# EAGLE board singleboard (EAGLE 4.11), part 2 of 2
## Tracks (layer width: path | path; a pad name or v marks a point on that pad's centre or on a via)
-15V  (via drill 0.61)
  Top 0.635: v123.83,21.59 v123.83,16.51
  Bottom 0.635: 180.97,20.32 187.32,13.97 U$1.BB2 | 180.97,20.32 179.71,21.59 v123.83,21.59 55.88,21.59 55.88,13.97 U$1.DB2 | v123.83,16.51 123.83,13.97 U$1.CB2 | 180.97,20.32 250.82,20.32 257.18,13.97 U$1.AB2
A15U1  (via drill 0.61)
  Top 0.254: E2.4 244.47,83.19 244.47,84.46 E2.2 245.75,87 245.75,88.27 E2.1 | E13.10 205.1,78.11 205.1,76.84 E13.9 203.84,74.3 203.84,24.77 v209.55,19.05 | R12.1 R11.2 | E13.5 197.49,79.38 197.49,80.65 E13.4 196.22,83.19 196.22,84.46 E13.2
  Bottom 0.254: E13.12 204.47,83.82 201.93,81.28 E13.4 R12.1 | E13.5 E13.10 207.01,78.74 208.28,77.47 241.3,77.47 245.11,81.28 E2.4 | v209.55,19.05 209.55,13.97 U$1.AU2
A15V1
  Top 0.254: E8.2 212.72,51.44 212.72,52.71 E8.1 | E8.12 R13.2 R14.1 | E2.9 253.37,76.84 253.37,78.11 E2.10 | E8.9 220.34,41.28 220.34,42.55 E8.10
  Bottom 0.254: E8.2 214.63,50.8 217.17,48.26 E8.12 | E2.12 252.09,81.92 252.09,79.38 253.37,79.38 E2.10 | E8.4 214.63,45.72 217.17,43.18 E8.10 222.88,43.18 225.43,45.72 R14.1 | E2.9 260.35,69.85 260.35,39.37 223.52,39.37 222.25,40.64 E8.9
B17S1  (via drill 0.61)
  Top 0.254: E49.1 28.57,87 28.57,83.19 E49.4 33.02,81.28 E49.9 | E12.3 210.82,177.8 210.82,119.38 E10.4 | v177.8,82.55 177.8,114.3 E19.4
  Bottom 0.254: 208.28,115.57 208.91,116.21 212.72,116.21 E10.4 217.17,116.84 219.71,114.3 E10.10 | 208.28,115.57 207.01,114.3 E14.10 | 208.28,115.57 182.88,115.57 181.61,116.84 E19.4 | v177.8,82.55 111.12,82.55 108.58,80.01 80.01,80.01 77.47,77.47 40.64,77.47 39.37,76.2 E49.9
B17V1  (via drill 0.61)
  Top 0.254: E7.3 230.5,118.75 230.5,117.48 E7.4 229.24,114.94 229.24,90.81 E6.1 | E10.1 219.07,124.46 219.07,123.83 E10.13 | R15.2 R16.1 | v19.68,84.46 19.68,57.79 E52.1 | v147.96,90.17 147.96,53.98 E26.1
  Bottom 0.254: E14.13 207.01,121.92 207.65,121.29 211.46,121.29 212.09,120.65 218.44,120.65 219.71,121.92 E10.13 227.33,121.92 229.87,119.38 E7.3 | E6.13 237.49,86.36 234.95,88.9 E6.1 226.69,84.46 226.06,84.46 R15.2 224.79,83.82 222.25,86.36 E9.13 217.17,86.36 214.63,88.9 E9.1 212.09,88.9 210.82,90.17 v147.96,90.17 | E26.13 153.67,50.8 151.13,53.34 E26.1 146.05,53.34 143.51,50.8 E27.13 135.89,50.8 133.35,53.34 E27.1 130.81,53.34 129.54,54.61 21.59,54.61 18.41,51.44 | 18.41,51.44 19.05,50.8 E52.13 | 18.41,51.44 16.51,53.34 E52.1 | 21.59,86.36 19.05,88.9 E53.1 | v19.68,84.46 21.59,86.36 | 21.59,86.36 E53.13
C16U1
  Top 0.254: R24.1 R23.2 | E22.5 164.47,79.38 164.47,80.65 E22.4 163.19,83.19 163.19,84.46 E22.2 | E18.5 179.71,79.38 179.71,80.65 E18.4 | E18.12 187.32,84.46 187.32,85.73 E18.13
  Bottom 0.254: E22.4 R24.1 | E18.5 E18.10 | E18.13 E18.2 179.07,86.36 177.8,87.63 167.64,87.63 166.37,86.36 E22.2 | E18.4 181.61,81.28 184.15,83.82 E18.12
D01BINIT  (via drill 0.61)
  Top 0.254: v184.15,91.44 181.61,88.9 E18.1 | v196.85,91.44 197.49,90.81 197.49,89.54 E13.1 | v167.64,92.71 167.64,114.3 E23.4
  Bottom 0.254: v196.85,91.44 v184.15,91.44 168.91,91.44 v167.64,92.71
D01BTP2L  (via drill 0.61)
  Top 0.254: v178.44,123.19 178.44,145.42 E20.4
  Bottom 0.254: E23.2 166.37,121.92 167.64,123.19 v178.44,123.19 228.6,123.19 229.87,121.92 E7.2 E7.13
D01DEL1H  (via drill 0.61)
  Top 0.254: v170.18,77.47 169.54,78.11 169.54,102.87 | 169.54,102.87 169.54,145.42 E24.3 | v230.5,103.51 233.04,106.05 233.04,112.4 E7.5 | 169.54,102.87 v170.18,102.87
  Bottom 0.254: v170.18,77.47 163.83,77.47 158.12,71.76 106.05,71.76 100.33,77.47 80.01,77.47 77.47,74.93 73.66,74.93 72.39,73.66 E44.8 | v230.5,103.51 229.87,102.87 v170.18,102.87
D01DEL1L  (via drill 0.61)
  Top 0.254: E14.4 196.22,118.75 196.22,145.42 E15.4 | v210.19,110.49 208.91,111.76 v208.91,118.11
  Bottom 0.254: v210.19,110.49 228.6,110.49 229.87,111.76 E7.6 | v208.91,118.11 200.66,118.11 199.39,116.84 E14.4
D01DEL2  (via drill 0.61)
  Top 0.254: 98.42,69.85 v97.16,71.12 | 98.42,69.85 v98.42,57.15 98.42,53.98 E35.1 | v151.13,123.19 151.13,140.97 E24.1 | v102.23,120.65 101.6,120.02 101.6,73.03 98.42,69.85 | v112.39,50.8 109.86,53.34 v109.86,57.15
  Bottom 0.254: v97.16,71.12 69.85,71.12 64.77,76.2 E44.6 | v151.13,123.19 148.59,120.65 v102.23,120.65 | v112.39,50.8 113.03,50.8 115.57,48.26 IC2.1 | v98.42,57.15 v109.86,57.15
D01DEL3  (via drill 0.61)
  Top 0.254: v194.31,80.01 195.58,81.28 195.58,147.32 E15.3
  Bottom 0.254: v194.31,80.01 113.03,80.01 E36.8 | E15.11 204.47,147.32 201.93,149.86 E15.3
D01DEL4  (via drill 0.61)
  Top 0.254: E36.6 100.97,78.11 100.97,122.56 E37.1 | 194.94,147.32 194.94,177.17 E16.3 | 194.94,147.32 194.94,120.02 v194.31,119.38 v194.31,113.03 194.31,93.35 191.77,90.81 191.77,74.93 v186.69,69.85 | 194.94,147.32 v194.31,147.32
  Bottom 0.254: v194.31,119.38 E14.3 | v194.31,113.03 236.22,113.03 237.49,111.76 E7.9 | v194.31,147.32 E20.11 | v186.69,69.85 159.38,69.85 158.12,71.12 105.41,71.12 100.33,76.2 E36.6
D01DEL5  (via drill 0.61)
  Top 0.254: v174.62,125.73 175.9,127 175.9,138.43 177.8,140.34 177.8,147.32 178.44,147.96 | 178.44,147.96 E20.3 | v193.04,171.45 178.44,156.85 178.44,147.96
  Bottom 0.254: v174.62,125.73 168.91,125.73 166.37,123.19 163.83,123.19 158.75,118.11 87.63,118.11 E40.6 | v193.04,171.45 203.2,171.45 204.47,172.72 E16.9
D01DONEH  (via drill 0.61)
  Top 0.254: v176.53,33.02 176.53,105.41 E23.8 | v23.5,22.86 14.61,13.97 U$1.DS1
  Bottom 0.254: v176.53,33.02 166.37,22.86 v23.5,22.86
D01DONEL  (via drill 0.61)
  Top 0.254: v170.81,160.02 170.81,113.67 E23.9 | v135.89,179.71 135.89,182.88 137.16,184.15 E30.7
  Bottom 0.254: E16.8 206.38,170.82 207.65,170.82 207.65,173.36 207.01,173.99 184.78,173.99 v170.81,160.02 150.5,180.34 136.53,180.34 v135.89,179.71
D01INHIBIT  (via drill 0.61)
  Top 0.254: v221.62,15.24 221.62,37.47 E8.8
  Bottom 0.254: v221.62,15.24 222.88,13.97 U$1.AP2
D01INITL  (via drill 0.61)
  Top 0.254: E13.6 200.03,78.11 200.03,122.56 E14.1 200.03,126.37 200.03,146.69 E15.13 | E20.13 189.87,150.5 189.87,123.83 E19.13 186.69,121.92 186.69,122.56 v184.78,124.46
  Bottom 0.254: E15.13 204.47,152.4 201.93,154.94 E15.1 196.85,154.94 195.58,153.67 182.88,153.67 | v184.78,124.46 E19.1 | 182.88,153.67 184.15,152.4 E20.13 | 182.88,153.67 181.61,154.94 E20.1
D01LOADMDL  (via drill 0.61)
  Top 0.254: E49.10 E49.2 | v184.78,172.72 158.75,172.72 140.97,190.5 64.77,190.5 64.77,189.23 54.61,179.07 54.61,91.44 v46.99,83.82
  Bottom 0.254: E49.5 E49.10 41.91,78.74 v46.99,83.82 | v184.78,172.72 E16.6
D01MEMDONEL
  Bottom 0.254: E30.5 138.43,181.61 126.36,181.61 125.09,180.34 H05/H24.28
D01MEMSTARTL  (via drill 0.61)
  Top 0.254: v227.97,106.68 227.97,121.29 E7.1
  Bottom 0.254: E19.10 186.69,114.3 182.88,110.49 167.64,110.49 166.37,111.76 E23.6 163.19,111.76 163.19,108.59 165.1,106.68 v227.97,106.68
D01POWEROK  (via drill 0.61)
  Top 0.254: v134.62,115.57 130.81,111.76 130.81,66.68 128.27,64.14 128.27,27.94 137.16,19.05 v137.16,15.24
  Bottom 0.254: v134.62,115.57 160.02,115.57 163.83,119.38 E23.3 | v137.16,15.24 137.16,13.97 U$1.BV2
D01READH
  Top 0.254: E7.10 238.12,114.94 238.12,116.21 E7.11 236.85,118.75 236.85,125.73 238.12,127 238.12,187.33 237.49,187.96 200.03,187.96 200.03,181.61 | 194.31,173.99 194.31,179.07 196.85,181.61 200.03,181.61 | 194.31,173.99 194.31,171.45 193.04,170.18 193.04,116.84 E19.9 | 200.03,181.61 200.03,179.71 E16.4 197.49,177.17 197.49,175.9 E16.5 | 194.31,173.99 E24.13
  Bottom 0.254: E24.13 E24.2
D01READL  (via drill 0.61)
  Top 0.254: v210.19,178.44 v210.19,111.76 211.46,110.49 211.46,107.95 214,107.95 227.97,93.98 227.97,34.93 v227.33,34.29 | E16.10 205.1,175.9 205.1,177.17 E16.11 | v238.76,15.88 238.12,16.51 v238.12,23.5
  Bottom 0.254: v210.19,111.76 208.91,110.49 190.5,110.49 189.23,109.22 E19.8 | v210.19,178.44 209.55,177.8 E16.11 | v238.76,15.88 236.85,13.97 U$1.AK2 | v238.12,23.5 v227.33,34.29
D01RETURN  (via drill 0.61)
  Top 0.254: v217.81,15.24 217.81,61.6 E13.8
  Bottom 0.254: v217.81,15.24 219.07,13.97 U$1.AR2
D01SELECTH
  Top 0.254: E18.9 186.06,78.11 186.06,100.97 178.44,108.59 178.44,112.4 E19.5
D01SELECTL  (via drill 0.61)
  Top 0.254: v148.59,113.03 146.05,115.57 146.05,168.91 E30.2 137.16,181.61 139.7,184.15 E30.6
  Bottom 0.254: v148.59,113.03 177.8,113.03 179.07,111.76 E19.6
D01SELH  (via drill 0.61)
  Top 0.254: v177.16,128.91 177.16,121.92 E19.2 | v212.09,132.08 211.46,132.72 211.46,140.34 E11.6
  Bottom 0.254: v177.16,128.91 180.34,132.08 v212.09,132.08
D01SELL
  Top 0.254: E11.5 218.44,144.78 218.44,175.26 E12.11
D01SOURCE  (via drill 0.61)
  Top 0.254: v243.84,19.05 243.84,73.66 E2.6
  Bottom 0.254: v243.84,19.05 241.94,17.15 234.31,17.15 232.41,15.24 232.41,13.97 U$1.AL2
D01STROBE  (via drill 0.61)
  Top 0.254: v231.78,66.68 228.6,63.5 228.6,17.78 229.87,16.51 v229.87,15.24
  Bottom 0.254: v231.78,66.68 245.75,66.68 252.73,73.66 E2.8 | v229.87,15.24 229.87,13.97 U$1.AM2
D01STROBEL
  Top 0.254: R18.1 R17.2 142.24,175.26 E30.3
  Bottom 0.254: H05/H24.24 125.09,175.26 126.36,173.99 147.96,173.99 149.22,175.26 R17.2
D01WRITE  (via drill 0.61)
  Top 0.254: v215.26,15.24 215.26,38.74 E8.6
  Bottom 0.254: v215.26,15.24 216.53,13.97 U$1.AS2
D01WRITEH
  Top 0.254: E22.1 163.19,90.81 163.19,142.88 E24.5 164.47,145.42 164.47,146.69 E24.4
  Bottom 0.254: E20.5 179.07,144.78 177.8,146.05 167.64,146.05 166.37,147.32 E24.4
D01WRITEL
  Top 0.254: E45.2 E45.7 E46.2 E46.7 | E50.2 E50.7 E51.2 E51.7 | E42.2 E42.7 E43.2 84.45,180.98 | 84.45,180.98 87.63,184.15 87.63,189.87 140.34,189.87 167,163.2 167,151.13 163.83,151.13 162.56,149.86 162.56,82.55 163.19,81.92 163.19,78.11 E22.6 | 84.45,180.98 81.28,184.15 E43.7
  Bottom 0.254: E46.2 49.53,181.61 31.75,181.61 31.11,180.98 27.3,180.98 E51.7 | E45.7 55.24,168.28 67.31,168.28 67.94,168.91 77.47,168.91 78.11,168.28 79.38,168.28 E42.7
D02MEM0  (via drill 0.61)
  Top 0.254: v110.49,151.13 110.49,149.86 111.76,148.59 E32.3
  Bottom 0.254: v110.49,151.13 108.58,153.04 100.33,153.04 99.69,153.67 98.42,153.67 97.16,154.94 H04/H23.8
D02MEM1
  Bottom 0.254: E32.5 110.49,158.75 98.42,158.75 97.16,160.02 H04/H23.12
D02MEM2
  Top 0.254: E41.3 83.82,148.59 95.25,160.02 95.25,163.2 96.52,164.47 H04/H23.16
D02MEM3
  Top 0.254: E41.5 86.36,156.21 95.25,165.1 95.25,168.28 96.52,169.55 H04/H23.20
D02MEM4
  Top 0.254: E33.3 111.76,163.83 110.49,165.1 110.49,186.69 107.95,189.23 97.79,189.23 97.79,177.17 96.52,175.9 H04/H23.24
D02MEM5
  Bottom 0.254: E33.5 110.49,173.99 98.42,173.99 97.79,174.63 97.79,179.71 96.52,179.71 H04/H23.28
D02MEM6
  Bottom 0.254: E34.3 107.95,181.61 98.42,181.61 97.16,182.88 H04/H23.30
D02MEM7
  Bottom 0.254: E34.5 112.39,183.52 100.33,183.52 99.69,184.15 98.42,184.15 97.16,185.42 H04/H23.32
D02MEM8  (via drill 0.61)
  Top 0.254: v139.7,151.13 E28.3
  Bottom 0.254: v139.7,151.13 126.36,151.13 125.09,152.4 H05/H24.6
D02MEM9
  Bottom 0.254: E28.5 140.34,153.04 128.27,153.04 127.64,153.67 126.36,153.67 125.09,154.94 H05/H24.8
D02MEM10
  Bottom 0.254: E29.3 137.79,164.47 133.35,164.47 130.18,161.29 126.36,161.29 125.09,160.02 H05/H24.12
D02MEM11
  Bottom 0.254: E29.5 138.43,166.37 126.36,166.37 125.09,165.1 H05/H24.16
D03BEMA0L  (via drill 0.61)
  Top 0.254: v225.43,100.97 214.63,111.76 E10.6 | v250.82,15.24 v250.82,95.89
  Bottom 0.254: v225.43,100.97 230.5,95.89 v250.82,95.89 | v250.82,15.24 250.82,13.97 U$1.AD2
D03BEMA1L  (via drill 0.61)
  Top 0.254: v248.28,106.68 249.56,105.41 v249.56,15.24
  Bottom 0.254: v248.28,106.68 247.01,107.95 223.52,107.95 222.25,109.22 E10.8 | v249.56,15.24 249.56,13.97 U$1.AE2
D03BEMA2L  (via drill 0.61)
  Top 0.254: v206.38,105.41 206.38,108.59 E14.8 | v241.94,105.41 242.57,104.78 v242.57,15.24
  Bottom 0.254: v241.94,105.41 v206.38,105.41 | v242.57,15.24 242.57,13.97 U$1.AH2
D03BMA0  (via drill 0.61)
  Top 0.254: v252.09,90.17 252.09,42.55 E1.9
  Bottom 0.254: v252.09,90.17 247.01,95.25 32.38,95.25 11.43,116.21 11.43,165.1 H01/H20.16
D03BMA1
  Top 0.254: E1.1 248.28,55.25 248.28,105.41 247.01,106.68 247.01,107.32 252.73,113.03 260.35,113.03 260.35,172.72 241.3,191.77 13.97,191.77 13.97,172.09 12.7,170.82 H01/H20.20
D03BMA2  (via drill 0.61)
  Top 0.254: v11.43,70.49 11.43,173.36 12.7,174.63 H01/H20.24
  Bottom 0.254: v11.43,70.49 20.32,61.6 185.42,61.6 191.13,55.88 213.36,55.88 219.71,49.53 227.33,49.53 229.87,46.99 232.41,46.99 E5.9
D03BMA3  (via drill 0.61)
  Top 0.254: v10.16,73.03 10.79,73.66 10.79,177.8 12.7,179.71 H01/H20.28
  Bottom 0.254: v10.16,73.03 15.88,67.31 227.33,67.31 227.33,57.79 226.69,57.15 219.07,57.15 219.07,52.71 219.71,52.07 228.6,52.07 229.87,53.34 E5.1
D03BMA4  (via drill 0.61)
  Top 0.254: v180.34,34.29 186.69,40.64 E17.9
  Bottom 0.254: v180.34,34.29 16.51,34.29 6.99,43.82 6.99,182.88 H01/H20.30
D03BMA5  (via drill 0.61)
  Top 0.254: v11.43,60.96 8.89,63.5 8.89,180.98 12.7,184.79 H01/H20.32
  Bottom 0.254: v11.43,60.96 47.62,60.96 52.7,55.88 189.87,55.88 189.87,52.71 189.23,52.07 182.88,52.07 181.61,53.34 E17.1
D03BMA6  (via drill 0.61)
  Top 0.254: v164.47,135.26 168.91,130.81 168.91,44.45 E21.9
  Bottom 0.254: v164.47,135.26 162.56,137.16 51.44,137.16 41.91,146.69 41.91,151.77 40.64,151.77 H02/H21.6
D03BMA7  (via drill 0.61)
  Top 0.254: v153.67,128.91 153.67,85.73 162.56,76.84 162.56,55.88 E21.1
  Bottom 0.254: v153.67,128.91 151.13,131.45 54.61,131.45 39.37,146.69 39.37,154.94 H02/H21.8
D03BMA8
  Top 0.254: E47.9 50.16,46.36 50.16,55.88 45.72,60.33 45.72,142.88 41.91,146.69 41.91,158.12 40.64,159.39 H02/H21.12
D03BMA9
  Top 0.254: E47.1 45.09,56.52 45.09,140.97 39.37,146.69 39.37,163.2 40.64,164.47 H02/H21.16
D03BMA10
  Top 0.254: E48.9 41.91,44.45 41.91,55.25 44.45,57.79 44.45,140.34 38.73,146.05 38.73,167.64 40.64,169.55 H02/H21.20
D03BMA11
  Top 0.254: E48.1 28.57,55.25 28.57,76.84 29.21,77.47 35.56,77.47 35.56,76.2 36.83,74.93 41.91,74.93 41.91,141.61 38.1,145.42 38.1,172.09 40.64,174.63 H02/H21.24
D03BTP2  (via drill 0.61)
  Top 0.254: v191.13,125.73 191.77,125.1 191.77,120.65 E19.11 | v125.73,126.37 125.73,183.52 124.46,184.79 H05/H24.32
  Bottom 0.254: v191.13,125.73 189.87,127 168.91,127 166.37,124.46 E23.1 127.64,124.46 v125.73,126.37
D03EA0
  Bottom 0.254: E4.1 245.11,154.94 241.3,158.75 120.65,158.75 114.94,164.47 102.87,164.47 99.69,161.29 95.25,161.29 85.09,151.13 70.48,151.13 69.22,152.4 H03/H22.6
D03EA1  (via drill 0.61)
  Top 0.254: v73.03,133.35 72.39,133.99 72.39,144.15 69.85,146.69 69.85,153.04 68.58,154.31 H03/H22.8
  Bottom 0.254: v73.03,133.35 212.09,133.35 214.63,130.81 260.35,130.81 260.35,140.34 259.71,140.97 256.54,140.97 255.27,142.24 E4.9
D03EA2  (via drill 0.61)
  Top 0.254: v245.75,132.08 245.75,125.1 E3.1 | v71.12,135.89 67.31,139.7 67.31,158.12 68.58,159.39 H03/H22.12
  Bottom 0.254: v245.75,132.08 244.47,133.35 213.36,133.35 212.72,133.99 73.66,133.99 71.75,135.89 v71.12,135.89
D03EMA0H
  Top 0.254: 219.07,137.8 211.46,130.18 211.46,123.83 E10.2 | 219.07,137.8 E11.8 | 219.07,137.8 219.07,170.82 E12.9
  Bottom 0.254: E12.9 222.25,172.72 229.87,180.34 JP1.1
D03EMA0L  (via drill 0.61)
  Top 0.254: 211.46,156.85 211.46,175.9 E12.4 | 211.46,156.85 E11.1 | v215.9,146.05 211.46,146.05 211.46,156.85
  Bottom 0.254: E4.6 245.11,142.24 243.84,143.51 223.52,143.51 222.25,142.24 E11.9 219.71,142.24 v215.9,146.05 | JP1.3 233.04,180.34 231.78,181.61 224.79,181.61 222.25,179.07 215.9,179.07 214.63,177.8 E12.4
D03EMA1H
  Top 0.254: 222.88,140.97 222.88,142.88 | 222.88,140.97 222.88,121.29 E10.12 | 222.88,142.88 E11.10 | 222.88,142.88 222.88,173.36 E12.10 | 222.88,140.97 234.31,140.97 234.95,141.61 234.95,165.74 233.68,167.01 JP2.3
D03EMA1L
  Bottom 0.254: 234.95,168.91 234.95,170.82 234.31,171.45 218.44,171.45 214.63,175.26 E12.5 | 234.95,168.91 233.04,168.91 231.78,167.64 JP2.1 | 247.65,146.05 223.52,146.05 222.25,147.32 E11.11 | 247.65,146.05 E4.8 | 234.95,168.91 236.85,168.91 248.28,157.48 248.28,146.05 247.65,146.05
D03EMA2H  (via drill 0.61)
  Top 0.254: v203.84,146.05 203.84,121.29 E14.12
  Bottom 0.254: v203.84,146.05 207.01,146.05 212.09,151.13 218.44,151.13 219.71,149.86 E11.12 226.69,149.86 231.14,154.31 JP3.1
D03EMA2L  (via drill 0.61)
  Top 0.254: v241.94,147.32 241.94,116.21 E3.6
  Bottom 0.254: v241.94,147.32 234.31,154.94 JP3.3 233.04,154.94 231.78,156.21 226.06,156.21 222.25,152.4 E11.13
D03MA0L
  Top 0.254: E1.8 252.09,36.2 252.09,13.97 U$1.AD1
D03MA1L
  Top 0.254: E1.6 248.28,38.74 248.28,13.97 U$1.AE1
D03MA2L
  Top 0.254: E5.8 241.3,35.56 241.3,13.97 U$1.AH1
D03MA3L
  Top 0.254: E5.6 235.59,36.2 235.59,15.88 236.85,14.61 238.12,14.61 238.12,13.97 U$1.AJ1
D03MA4L
  Top 0.254: E17.8 182.88,33.02 182.88,13.97 U$1.BD1
D03MA5L
  Top 0.254: E17.6 178.44,38.74 178.44,13.97 U$1.BE1
D03MA6L
  Top 0.254: E21.8 172.09,37.47 172.09,13.97 U$1.BH1
D03MA7L
  Top 0.254: E21.6 168.28,37.47 168.28,13.97 U$1.BJ1
D03MA8L
  Top 0.254: E47.8 49.53,31.75 49.53,13.97 U$1.DD1
D03MA9L
  Top 0.254: E47.6 46.35,38.74 46.35,13.97 U$1.DE1
D03MA10L
  Top 0.254: E48.8 38.1,13.97 U$1.DH1
D03MA11L
  Top 0.254: E48.6 34.92,36.2 34.92,13.97 U$1.DJ1
D03MCBMB0L
  Bottom 0.254: E46.1 49.53,179.07 42.55,179.07 41.27,180.34 H02/H21.28
D03MCBMB1L
  Bottom 0.254: E46.6 53.98,183.52 44.45,183.52 43.81,184.15 42.55,184.15 41.27,182.88 H02/H21.30
D03MCBMB2L
  Bottom 0.254: E51.6 30.48,185.42 H02/H21.32
D03MCBMB3L
  Bottom 0.254: E50.1 21.59,153.67 14.61,153.67 13.34,152.4 H01/H20.6
D03MCBMB4L
  Bottom 0.254: E50.6 24.13,158.75 14.61,158.75 13.97,158.12 13.97,155.58 12.7,155.58 H01/H20.8
D03MCBMB5L
  Bottom 0.254: E51.1 21.59,173.99 14.61,173.99 13.97,173.36 13.97,160.66 12.7,160.66 H01/H20.12
D03MCBMB6L
  Bottom 0.254: E45.1 53.34,165.1 H03/H22.16
D03MCBMB7L
  Bottom 0.254: E45.6 57.78,172.09 66.04,172.09 67.94,170.18 H03/H22.20
D03MCBMB8L  (via drill 0.61)
  Top 0.254: v75.56,176.53 75.56,167.01 78.74,163.83 E42.1
  Bottom 0.254: v75.56,176.53 70.48,176.53 69.22,175.26 H03/H22.24
D03MCBMB9L
  Bottom 0.254: E42.6 80.01,173.99 67.94,173.99 67.31,174.63 67.31,180.34 H03/H22.28
D03MCBMB10L
  Bottom 0.254: E43.1 74.93,181.61 70.48,181.61 69.22,182.88 H03/H22.30
D03MCBMB11L
  Bottom 0.254: E43.6 81.92,183.52 72.39,183.52 71.75,184.15 70.48,184.15 69.22,185.42 H03/H22.32
D03MEMSTART  (via drill 0.61)
  Top 0.254: v123.19,116.84 123.19,168.28 124.46,169.55 H05/H24.20
  Bottom 0.254: 210.82,118.11 212.09,119.38 E10.3 217.17,119.38 219.71,116.84 E10.11 | 210.82,118.11 209.55,116.84 E14.11 | v123.19,116.84 125.73,114.3 E23.5 166.37,114.3 170.18,118.11 177.8,118.11 179.07,119.38 E19.3 181.61,119.38 182.88,120.65 208.28,120.65 210.82,118.11
D04MD0L  (via drill 0.61)
  Top 0.254: 233.68,83.82 233.04,83.82 233.04,57.79 229.24,53.98 229.24,20.96 234.95,15.24 234.95,13.97 U$1.AK1 | 233.68,83.82 E6.12 | v66.67,130.18 66.67,165.74 55.88,176.53 E46.3 | v231.14,127 233.68,124.46 233.68,83.82
  Bottom 0.254: v66.67,130.18 69.22,127.64 205.74,127.64 206.38,127 v231.14,127
D04MD1L  (via drill 0.61)
  Top 0.254: v234.95,82.55 236.85,80.65 236.85,69.22 | 236.85,69.22 v236.85,15.88 | v233.68,15.24 233.68,13.97 U$1.AL1 | 236.85,69.22 241.3,73.66 241.3,90.17 240.66,90.81 240.66,191.14 64.14,191.14 E46.5
  Bottom 0.254: v236.85,15.88 236.22,15.24 v233.68,15.24 | v234.95,82.55 E6.2
D04MD2L  (via drill 0.61)
  Top 0.254: 219.07,65.41 v219.07,19.05 | 219.07,65.41 219.07,81.92 E9.12 | v228.6,16.51 228.6,13.97 U$1.AM1 | v37.47,144.15 37.47,174.63 30.48,181.61 E51.5 | v208.91,100.97 208.91,75.57 219.07,65.41
  Bottom 0.254: v219.07,19.05 221.62,16.51 v228.6,16.51 | v37.47,144.15 80.01,101.6 134.62,101.6 135.25,100.97 v208.91,100.97
D04MD3L  (via drill 0.61)
  Top 0.254: 215.26,86.36 219.07,86.36 219.07,85.73 219.71,85.09 227.33,85.09 227.33,38.74 224.16,35.56 224.16,13.97 U$1.AP1 | 215.26,86.36 E9.2 | v210.19,99.7 215.26,94.62 215.26,86.36
  Bottom 0.254: v210.19,99.7 135.25,99.7 133.99,100.97 27.94,100.97 E50.3
D04MD4L  (via drill 0.61)
  Top 0.254: 153.03,46.36 153.03,42.55 153.67,41.91 163.19,41.91 163.19,15.88 165.1,13.97 U$1.BK1 | 153.03,46.36 E26.12 | v34.92,99.7 34.92,156.85 30.48,161.29 E50.5 | v151.13,96.52 153.03,94.62 153.03,46.36
  Bottom 0.254: v34.92,99.7 38.1,96.52 v151.13,96.52
D04MD5L  (via drill 0.61)
  Top 0.254: 149.22,48.9 149.22,41.28 153.67,36.83 158.12,36.83 158.75,37.47 161.93,37.47 161.93,13.97 U$1.BL1 | 149.22,48.9 E26.2 | v36.2,147.32 36.2,165.74 27.94,173.99 E51.3 | v146.69,105.41 149.22,102.87 149.22,48.9
  Bottom 0.254: v36.2,147.32 59.69,123.83 66.67,123.83 80.01,110.49 85.09,110.49 90.17,105.41 v146.69,105.41
D04MD6L  (via drill 0.61)
  Top 0.254: U$1.BM1 160.66,13.97 161.29,14.61 161.29,36.83 159.38,36.83 158.75,36.2 146.69,36.2 144.78,38.1 144.78,43.18 E27.12 137.16,50.8 v137.16,144.15 | v64.14,144.15 64.14,153.04 55.88,161.29 E45.3
  Bottom 0.254: v64.14,144.15 64.77,143.51 120.02,143.51 120.65,144.15 123.19,144.15 123.83,143.51 136.53,143.51 v137.16,144.15
D04MD7L  (via drill 0.61)
  Top 0.254: U$1.BP1 152.4,13.97 137.79,28.58 137.79,46.99 v135.25,49.53 134.62,50.17 134.62,101.6 v135.25,102.24 | v65.41,122.56 65.41,161.93 58.42,168.91 E45.5
  Bottom 0.254: v135.25,49.53 134.62,49.53 133.35,50.8 E27.2 | v65.41,122.56 85.72,102.24 v135.25,102.24
D04MD8L  (via drill 0.61)
  Top 0.254: 27.94,90.17 21.59,90.17 20.95,89.54 20.95,85.73 E53.12 | 27.94,90.17 27.94,17.78 31.75,13.97 U$1.DK1 | v30.48,158.75 29.21,157.48 29.21,91.44 27.94,90.17
  Bottom 0.254: v30.48,158.75 57.15,158.75 59.69,161.29 71.75,161.29 74.93,164.47 81.92,164.47 E42.3
D04MD9L  (via drill 0.61)
  Top 0.254: U$1.DL1 28.57,13.97 27.3,15.24 27.3,49.53 21.59,49.53 19.05,46.99 19.05,44.45 13.97,44.45 12.7,45.72 12.7,83.82 E53.2 17.14,88.27 17.14,163.2 v20.32,166.37
  Bottom 0.254: v20.32,166.37 82.55,166.37 E42.5
D04MD10L  (via drill 0.61)
  Top 0.254: E52.12 25.4,45.72 25.4,13.97 U$1.DM1 | v51.44,50.8 51.44,81.28 74.93,104.78 74.93,146.05 80.01,151.13 80.01,156.21 82.55,158.75 82.55,175.26 83.82,176.53 E43.3
  Bottom 0.254: v51.44,50.8 50.16,49.53 25.4,49.53 24.13,48.26 E52.12
D04MD11L  (via drill 0.61)
  Top 0.254: v20.32,46.99 20.95,46.36 20.95,26.67 24.77,22.86 24.77,19.05 20.95,15.24 20.95,13.97 U$1.DP1 | v47.62,59.69 47.62,78.74 74.3,105.41 74.3,187.33 84.45,187.33 E43.5
  Bottom 0.254: v20.32,46.99 16.51,50.8 E52.2 14.61,51.44 13.34,51.44 13.34,53.98 14.61,55.25 43.18,55.25 v47.62,59.69
GND  (via drill 0.61)
  Top 0.635: E19.12 182.25,113.67 182.25,111.13 E19.7 | E19.12 v190.5,121.92 | E12.1 212.72,184.79 212.72,183.52 E12.2 215.26,180.98 215.26,172.09 E12.7 | E3.7 248.28,111.13 248.28,137.8 E4.7 | E20.12 182.25,144.15 182.25,141.61 E20.7 180.97,139.07 180.97,126.37 E19.12 | E16.7 196.22,168.28 196.22,154.31 E15.2 | H01/H20.33 H01/H20.31 H01/H20.29 H01/H20.27 H01/H20.25 H01/H20.23 H01/H20.21 H01/H20.19 H01/H20.17 H01/H20.15 H01/H20.13 H01/H20.11 H01/H20.9 H01/H20.7 H01/H20.5 H01/H20.3 H01/H20.1 | H02/H21.33 H02/H21.31 H02/H21.29 H02/H21.27 H02/H21.25 H02/H21.23 H02/H21.21 H02/H21.19 H02/H21.17 H02/H21.15 H02/H21.13 H02/H21.11 H02/H21.9 H02/H21.7 H02/H21.5 H02/H21.3 H02/H21.1 | H05/H24.33 H05/H24.31 H05/H24.29 H05/H24.27 H05/H24.25 H05/H24.23 H05/H24.21 H05/H24.19 H05/H24.17 H05/H24.15 H05/H24.13 H05/H24.11 H05/H24.9 H05/H24.7 H05/H24.5 H05/H24.3 H05/H24.1 | H03/H22.33 H03/H22.31 H03/H22.29 H03/H22.27 H03/H22.25 H03/H22.23 H03/H22.21 H03/H22.19 H03/H22.17 H03/H22.15 H03/H22.13 H03/H22.11 H03/H22.9 H03/H22.7 H03/H22.5 H03/H22.3 H03/H22.1 | H04/H23.33 H04/H23.31 H04/H23.29 H04/H23.27 H04/H23.25 H04/H23.23 H04/H23.21 H04/H23.19 H04/H23.17 H04/H23.15 H04/H23.13 H04/H23.11 H04/H23.9 H04/H23.7 H04/H23.5 H04/H23.3 H04/H23.1 | v22.23,15.24 22.23,13.97 U$1.DN2 | U$1.DF1 43.18,13.97 R10.2 | U$1.DT2 11.43,13.97 v12.7,15.24 14.61,17.15 14.61,37.47 E52.7 | U$1.CC1 120.65,13.97 120.65,15.24 v114.3,15.24 113.03,13.97 U$1.CF1 111.12,13.97 109.86,15.24 93.98,15.24 93.98,13.97 U$1.CN2 92.08,13.97 90.81,15.24 80.64,15.24 | 80.64,15.24 80.64,13.97 U$1.CT2 | 80.64,20.32 80.64,15.24
  Top 0.635: 80.64,20.32 80.64,37.47 E38.7 78.11,41.28 78.11,62.87 D2.A | 80.64,20.32 59.05,20.32 52.7,13.97 U$1.DC1 | R27.1 D4.A 114.3,71.12 E31.7 | 83.19,108.59 92.71,99.06 R29.1 D5.A | 83.19,108.59 82.55,109.22 E40.7 | E37.7 96.52,106.68 D5.A | 95.89,71.76 93.98,69.85 R19.1 | 95.89,71.76 97.79,73.66 E36.7 | D2.A R21.1 74.93,63.5 64.77,73.66 E44.7 | E39.7 78.74,71.12 D2.A | 95.89,71.76 95.89,97.16 96.52,97.79 D5.A | U$1.AN2 225.43,13.97 v225.43,15.24 226.06,15.88 R14.2 | U$1.AF1 245.75,13.97 v245.75,15.24 245.75,37.47 E1.7 | U$1.AC1 255.91,13.97 264.16,22.23 264.16,29.85 259.08,34.93 R4.2 | v176.53,15.24 176.53,13.97 U$1.BF1 | U$1.BT2 142.88,13.97 138.43,18.42 138.43,26.67 131.44,33.66 131.44,37.47 E27.7 130.18,40.01 130.18,62.23 129.54,62.87 R25.1 | U$1.BN2 157.48,13.97 v158.75,15.24 160.02,16.51 R7.2 | U$1.AT2 212.72,13.97 v212.72,15.24 212.72,37.47 E8.7 | U$1.BC1 186.06,13.97 187.32,15.24 191.77,15.24 191.77,33.66 193.04,34.93 R6.2 193.04,36.2 194.31,37.47 194.31,69.22 193.04,70.49 R12.2 | 83.19,108.59 83.19,142.88 86.36,146.05 E41.4
  Bottom 0.635: 177.8,107.95 167.64,107.95 166.37,109.22 E23.7 | 177.8,107.95 179.07,109.22 E19.7 | 195.58,107.95 196.85,109.22 E14.7 | 177.8,107.95 195.58,107.95 | v190.5,121.92 E14.2 | 195.58,107.95 210.82,107.95 212.09,109.22 E10.7 | E16.7 199.39,170.18 200.66,168.91 210.82,168.91 212.09,170.18 E12.7 214.63,170.18 219.07,165.74 233.68,165.74 235.59,167.64 JP2.5 | E20.2 181.61,152.4 184.15,149.86 E20.12 194.31,149.86 196.85,152.4 E15.2 201.93,152.4 204.47,149.86 E15.12 | E7.7 232.41,109.22 233.68,110.49 243.84,110.49 245.11,109.22 E3.7 | R2.2 258.44,139.7 257.18,138.43 248.92,138.43 247.65,139.7 E4.7 245.11,139.7 243.84,138.43 210.82,138.43 | 177.8,138.43 179.07,139.7 E20.7 | 177.8,138.43 177.16,137.8 168.28,137.8 166.37,139.7 E24.7 163.83,139.7 163.19,140.34 149.22,140.34 E28.4 139.7,149.86 H05/H24.3 | 195.58,138.43 196.85,139.7 E15.7 | 177.8,138.43 195.58,138.43 | 210.82,138.43 212.09,139.7 E11.7 | 195.58,138.43 210.82,138.43 | E51.4 27.94,172.72 H01/H20.21 | E50.4 27.94,157.48 H01/H20.9 | E46.4 55.88,175.26 H02/H21.23 | E45.4 55.88,160.02 H02/H21.11 | H01/H20.33 15.88,187.96 17.78,189.87 40.64,189.87 42.55,187.96 H02/H21.33 | E30.4 139.7,175.26 H05/H24.23 | R18.2 E29.4 139.7,160.02 H05/H24.11 | E43.4 83.82,175.26 H03/H22.23 | H03/H22.3 83.82,149.86 E41.4 88.27,145.42 96.52,145.42 98.42,147.32 H04/H23.1 | E42.4 83.82,160.02 H03/H22.11 | E34.4 111.76,175.26 H04/H23.23 | H04/H23.3 111.76,149.86 E32.4 116.2,145.42 124.46,145.42 126.36,147.32 H05/H24.1 | E33.4 111.76,160.02 H04/H23.11 | H02/H21.1 43.81,147.32 45.72,145.42 68.58,145.42 70.48,147.32 H03/H22.1 | U$1.DC2 50.8,13.97 49.53,15.24 44.45,15.24 43.18,13.97 U$1.DF2 41.27,13.97 40.01,15.24 v22.23,15.24 21.59,14.61
  Bottom 0.635: 21.59,14.61 22.23,13.97 U$1.DN2 | 21.59,14.61 20.95,15.24 v12.7,15.24 11.43,13.97 U$1.DT2 | 27.94,36.83 17.78,36.83 16.51,38.1 E52.7 | 27.94,36.83 29.21,38.1 E48.7 | 27.94,36.83 41.27,36.83 42.55,35.56 R10.2 43.81,35.56 46.35,38.1 E47.7 49.53,38.1 50.8,36.83 83.82,36.83 | U$1.CC2 120.65,13.97 119.38,15.24 v114.3,15.24 113.03,13.97 U$1.CF2 111.12,13.97 109.86,15.24 90.81,15.24 | 90.81,15.24 82.55,15.24 81.28,13.97 U$1.CT2 | 90.81,15.24 92.08,13.97 U$1.CN2 | 83.82,36.83 96.52,36.83 97.79,38.1 E35.7 | 83.82,36.83 82.55,38.1 E38.7 | R25.1 D3.A 126.36,62.87 114.94,62.87 D4.A | E53.7 16.51,73.66 17.78,72.39 27.94,72.39 29.21,73.66 E49.7 31.75,73.66 33.02,72.39 60.96,72.39 62.23,73.66 E44.7 | D2.A 79.38,62.87 90.81,62.87 D1.A R19.1 R27.1 | 227.97,72.39 229.24,73.66 E6.7 | 227.97,72.39 226.69,71.12 R16.2 217.17,71.12 214.63,73.66 E9.7 212.09,73.66 210.82,72.39 194.94,72.39 | 227.97,72.39 243.84,72.39 245.11,73.66 E2.7 | R24.2 160.66,71.12 163.19,73.66 E22.7 166.37,73.66 168.28,71.76 183.51,71.76 | 194.94,72.39 196.22,73.66 E13.7 | 194.94,72.39 193.68,71.12 R12.2 184.15,71.12 183.51,71.76 | 183.51,71.76 181.61,73.66 E18.7 | U$1.AC2 254,13.97 251.46,16.51 248.92,16.51 246.38,13.97 U$1.AF2 245.75,13.97 v245.75,15.24 | v225.43,15.24 225.43,13.97 U$1.AN2 | 248.92,36.83 250.19,35.56 R4.2 | 248.92,36.83 247.65,38.1 E1.7 | 248.92,36.83 233.68,36.83 232.41,38.1 E5.7 229.24,38.1 226.69,35.56 R14.2 225.43,35.56 224.16,36.83 215.9,36.83 214.63,38.1 E8.7 196.22,38.1 193.68,35.56 R6.2 184.15,35.56 182.88,36.83 | 177.16,14.61 177.8,15.24 182.88,15.24 184.15,13.97 U$1.BC2 | 177.16,14.61 176.53,13.97 U$1.BF2 174.62,13.97 173.35,15.24 v158.75,15.24 154.31,15.24
  Bottom 0.635: 177.16,14.61 v176.53,15.24 | 154.31,15.24 146.05,15.24 144.78,13.97 U$1.BT2 | 154.31,15.24 155.57,13.97 U$1.BN2 | 144.78,36.83 134.62,36.83 133.35,38.1 E27.7 | 144.78,36.83 146.05,38.1 E26.7 | 144.78,36.83 158.12,36.83 159.38,35.56 R7.2 160.66,35.56 163.19,38.1 E21.7 166.37,38.1 167.64,36.83 182.88,36.83 | v212.72,15.24 212.72,13.97 U$1.AT2 | 182.88,36.83 181.61,38.1 E17.7
  pour Top: 0,203.2 264.16,203.2 264.16,20.32 0,20.32
  pour Bottom: 0,203.2 264.16,203.2 264.16,20.32 0,20.32
N$1
  Top 0.254: R2.1 R1.2 | E4.2 E4.13 253.37,151.77 253.37,150.5 E4.12 252.09,147.96 252.09,144.78 | E3.5 245.75,114.94 245.75,116.21 E3.4 244.47,118.75 244.47,120.02 E3.2 244.47,123.83 244.47,142.88 E4.5 | E4.5 245.75,145.42 245.75,146.69 E4.4 | 252.09,144.78 E4.10 | E4.5 252.09,144.78
  Bottom 0.254: E4.12 R2.1
N$2
  Top 0.254: E5.12 238.12,48.9 238.12,50.17 E5.13 | E1.4 245.75,45.09 245.75,43.82 E1.5 | E1.13 253.37,50.17 253.37,48.9 E1.12 R3.2 R4.1
  Bottom 0.254: E5.13 E1.2 E1.13 | E5.10 E1.5 E1.10 255.27,43.18 257.81,45.72 R4.1
N$3
  Top 0.254: E31.9 123.83,76.84 123.83,78.11 E31.10 | D3.C R25.2 C3.2
  Bottom 0.254: E31.9 D3.C
N$4
  Top 0.254: E17.5 179.71,43.82 179.71,45.09 E17.4 182.25,47.63 182.25,50.8 | E17.12 187.32,48.9 187.32,50.17 E17.13 182.25,50.8 | 182.25,50.8 E17.2 | E5.5 230.5,43.82 230.5,45.09 E5.4 233.04,47.63 233.04,48.9 E5.2 | R5.2 R6.1
  Bottom 0.254: E17.10 189.23,43.18 191.77,45.72 R6.1 | E5.4 229.87,45.72 228.6,46.99 194.94,46.99 193.68,48.26 R5.2 E17.12
N$5
  Top 0.254: E37.5 98.42,114.94 98.42,116.21 E37.4 | D5.C R29.2 C5.2
  Bottom 0.254: E37.5 97.79,114.3 95.25,111.76 C5.2
N$6  (via drill 0.61)
  Top 0.254: E21.12 172.09,48.9 172.09,50.17 E21.13 | R8.2 R7.1 E21.4 164.47,45.09 164.47,43.82 E21.5 | E47.10 53.98,45.09 53.98,46.36 E47.12 55.24,48.9 55.24,50.17 E47.13 59.05,50.8 v59.05,57.15 | v165.1,57.15 167,55.25 167,50.8 E21.2
  Bottom 0.254: R8.2 161.29,48.26 163.83,50.8 E21.2 E21.13 | E21.5 E21.10 | v59.05,57.15 60.33,58.42 158.12,58.42 159.38,57.15 v165.1,57.15
N$7
  Top 0.254: E12.13 232.41,171.45 232.41,146.69 233.68,145.42 JP4.4
  Bottom 0.254: JP4.2 JP4.4 JP4.6
N$8
  Bottom 0.254: E6.11 234.95,81.28 232.41,83.82 E6.3 229.87,83.82 228.6,82.55 218.44,82.55 | E49.3 31.75,83.82 33.02,85.09 82.55,85.09 87.63,90.17 146.69,90.17 151.76,85.09 210.82,85.09 212.09,83.82 E9.3 217.17,83.82 218.44,82.55 | 218.44,82.55 219.71,81.28 E9.11
N$9
  Top 0.254: E39.5 80.64,79.38 80.64,80.65 E39.4 | D2.C R21.2 C2.2
  Bottom 0.254: E39.5 80.01,78.74 77.47,76.2 C2.2
N$10  (via drill 0.61)
  Top 0.254: E38.12 92.71,52.07 92.71,80.01 E39.12 | v74.3,48.26 74.3,45.72 IC1.7
  Bottom 0.254: v74.3,48.26 75.56,49.53 86.36,49.53 87.63,48.26 E38.12
N$11  (via drill 0.61)
  Top 0.254: v114.3,48.26 114.94,48.26 114.94,45.72 IC2.2 | E35.4 102.23,45.72 v102.23,49.53 102.23,59.06 v102.87,59.69 | v138.43,60.33 v138.43,85.09
  Bottom 0.254: v102.23,49.53 113.03,49.53 v114.3,48.26 | v138.43,85.09 127,85.09 125.73,83.82 E31.12 | v138.43,60.33 137.79,59.69 v102.87,59.69
N$12  (via drill 0.61)
  Top 0.254: v210.19,96.52 210.19,79.38 E9.6 | v102.87,99.06 103.5,99.7 103.5,132.72 87,149.23 85.72,149.23 85.09,148.59 85.09,146.05 84.45,145.42 82.55,145.42 82.55,152.4 83.82,153.67 E41.6
  Bottom 0.254: v210.19,96.52 207.65,99.06 v102.87,99.06
N$13
  Top 0.254: E39.10 88.27,78.11 88.27,76.84 E39.9 D1.C | R19.2 C1.2
  Bottom 0.254: D1.C R19.2
N$14  (via drill 0.61)
  Top 0.254: v227.33,134.62 235.59,126.37 235.59,94.62 240.66,89.54 240.66,75.57 E6.8 | E32.1 v106.68,142.24
  Bottom 0.254: v106.68,142.24 111.12,137.8 165.74,137.8 168.91,134.62 v227.33,134.62
N$15  (via drill 0.61)
  Top 0.254: v120.65,142.88 120.65,144.78 111.76,153.67 E32.6 | v224.79,135.89 226.69,133.99 226.69,98.43 228.6,96.52 228.6,78.74 E6.6
  Bottom 0.254: v120.65,142.88 125.09,138.43 166.37,138.43 168.91,135.89 v224.79,135.89
N$16  (via drill 0.61)
  Top 0.254: v35.56,48.26 35.56,71.12 E49.6
  Bottom 0.254: 149.22,44.45 152.4,44.45 153.67,45.72 E26.11 | 149.22,44.45 142.24,44.45 140.97,45.72 E27.11 | v35.56,48.26 36.83,46.99 129.54,46.99 130.81,48.26 E27.3 137.16,48.26 138.43,49.53 144.78,49.53 146.05,48.26 E26.3 147.96,47.63 149.22,47.63 149.22,44.45
N$17  (via drill 0.61)
  Top 0.254: v220.34,69.85 220.34,73.03 E9.8 | v85.09,68.58 83.82,69.85 83.82,104.14 78.74,109.22 E41.1
  Bottom 0.254: v220.34,69.85 219.07,68.58 v85.09,68.58
N$18
  Top 0.254: E44.9 70.48,76.84 70.48,78.11 E44.10 69.22,80.65 69.22,81.92 E44.12 70.48,84.46 70.48,85.73 E44.13 | E39.8 87,75.57 87,84.46 E39.13
  Bottom 0.254: E44.12 72.39,83.82 73.66,82.55 83.82,82.55 87.63,86.36 E39.13
N$19
  Top 0.254: C1.1 R20.1
  Bottom 0.254: E39.11 C1.1
N$20
  Top 0.254: C2.1 R22.1
  Bottom 0.254: R22.1 E39.3
N$21  (via drill 0.61)
  Top 0.254: E52.4 20.95,51.44 20.95,76.84 E53.10 | v161.29,73.66 161.29,51.44 156.84,46.99 156.84,45.09 E26.10
  Bottom 0.254: E6.10 237.49,78.74 235.59,80.65 231.78,80.65 E6.4 229.87,81.28 227.33,78.74 E9.10 219.71,78.74 217.17,81.28 E9.4 212.09,81.28 210.82,80.01 196.85,80.01 194.31,77.47 182.88,77.47 181.61,76.2 E18.6 179.07,76.2 177.8,74.93 162.56,74.93 v161.29,73.66 | 135.25,43.82 135.89,43.18 E27.10 141.6,43.18 142.88,41.91 152.4,41.91 153.67,43.18 E26.10 | 135.25,43.82 133.35,45.72 E27.4 130.81,45.72 129.54,44.45 17.78,44.45 | 135.25,43.82 138.43,46.99 144.78,46.99 146.05,45.72 E26.4 | 17.78,44.45 19.05,43.18 E52.10 | 17.78,44.45 16.51,45.72 E52.4 | E53.10 21.59,78.74 19.05,81.28 E53.4
N$22  (via drill 0.61)
  Top 0.254: E41.2 E41.7 | E32.2 E32.7 E33.2 E33.7 E34.2 E34.7 | E28.2 E28.7 140.34,158.12 | v179.07,97.79 185.42,91.44 185.42,76.2 E18.8 | v142.24,97.79 140.97,99.06 140.97,157.48 140.34,158.12 | 140.34,158.12 137.16,161.29 E29.2 E29.7
  Bottom 0.254: E41.2 84.45,144.15 106.05,144.15 E32.2 | v142.24,97.79 v179.07,97.79 | E32.7 115.57,148.59 130.81,148.59 133.99,145.42 135.25,145.42 E28.2
N$23
  Top 0.254: E39.6 79.38,78.11 79.38,84.46 E39.2 | E44.5 62.87,79.38 62.87,80.65 E44.4 61.59,83.19 61.59,84.46 E44.2 62.87,87 62.87,88.27 E44.1
  Bottom 0.254: E39.2 80.01,86.36 78.74,87.63 66.04,87.63 64.77,88.9 E44.1
N$24  (via drill 0.61)
  Top 0.254: v144.78,165.1 145.41,164.47 145.41,42.55 E26.6
  Bottom 0.254: v144.78,165.1 132.72,165.1 131.44,163.83 118.11,163.83 E33.6
N$25  (via drill 0.61)
  Top 0.254: v127,43.18 127,49.53 121.28,55.25 121.28,140.97 122.56,140.97 122.56,169.55 121.92,170.18 121.92,173.99 113.03,182.88 113.03,184.15 111.76,184.15 E34.6
  Bottom 0.254: v127,43.18 129.54,40.64 E27.6
N$26  (via drill 0.61)
  Top 0.254: v120.65,41.28 120.65,41.91 105.41,41.91 104.14,43.18 104.14,173.99 106.68,176.53 E34.1
  Bottom 0.254: v120.65,41.28 122.56,39.37 137.16,39.37 138.43,38.1 E27.8
N$27  (via drill 0.61)
  Top 0.254: v116.2,57.15 104.78,68.58 104.78,159.39 106.68,161.29 E33.1 | v151.13,57.15 152.4,55.88 152.4,40.64 E26.8
  Bottom 0.254: v116.2,57.15 v151.13,57.15
N$28
  Top 0.254: C3.1 R26.1
  Bottom 0.254: E31.11 C3.1
N$29  (via drill 0.61)
  Top 0.254: v139.06,92.71 143.51,97.16 143.51,165.1 139.7,168.91 E29.6
  Bottom 0.254: v139.06,92.71 7.62,92.71 7.62,48.26 E52.6
N$30  (via drill 0.61)
  Top 0.254: v132.72,36.2 133.99,37.47 133.99,113.67 135.89,115.57 135.89,142.88 133.35,145.42 133.35,160.02 134.62,161.29 E29.1
  Bottom 0.254: v132.72,36.2 124.46,36.2 121.28,39.37 25.4,39.37 24.13,38.1 E52.8
N$31
  Top 0.254: E38.6 79.38,42.55 79.38,61.6 83.19,65.41 83.19,87 E39.1
  Bottom 0.254: IC1.3 64.14,42.55 67.94,42.55 68.58,41.91 77.47,41.91 78.74,40.64 E38.6
N$32
  Top 0.254: E36.9 106.05,76.84 106.05,78.11 E36.10 108.58,80.65 108.58,81.92 E36.12 106.05,84.46 106.05,85.73 E36.13 | E31.8 126.36,75.57 126.36,84.46 E31.13
  Bottom 0.254: E36.12 107.95,83.82 109.22,85.09 121.92,85.09 123.19,86.36 E31.13
N$33
  Top 0.254: E31.5 116.2,79.38 116.2,80.65 E31.4 | D4.C R27.2 C4.2
  Bottom 0.254: E31.5 115.57,78.74 113.03,76.2 C4.2
N$34
  Top 0.254: C4.1 R28.1
  Bottom 0.254: R28.1 E31.3
N$35  (via drill 0.61)
  Top 0.254: v86.36,103.51 86.36,58.42 E38.1 | v64.14,53.34 64.14,48.9 IC1.1
  Bottom 0.254: v86.36,103.51 87,104.14 229.87,104.14 230.5,104.78 241.3,104.78 241.94,104.14 247.01,104.14 249.56,106.68 249.56,118.11 241.3,118.11 240.03,119.38 E7.12 | E38.1 v64.14,53.34
N$36
  Top 0.254: E48.12 37.47,48.9 37.47,50.17 E48.13 | E48.4 29.84,45.09 29.84,43.82 E48.5 E48.10 | E47.5 47.62,43.82 47.62,45.09 E47.4 R10.1 43.18,46.99 | 43.18,46.99 R9.2 | 43.18,46.99 46.99,50.8 E47.2
  Bottom 0.254: E48.13 E48.2 | E48.10 E47.5 | R9.2 E48.12
N$37
  Top 0.254: E31.6 114.94,78.11 114.94,84.46 E31.2 | E36.5 98.42,79.38 98.42,80.65 E36.4 97.16,83.19 97.16,84.46 E36.2 98.42,87 98.42,88.27 E36.1
  Bottom 0.254: E31.2 115.57,86.36 114.3,87.63 101.6,87.63 100.33,88.9 E36.1
N$38
  Top 0.254: E35.10 117.47,53.98 | 117.47,53.98 118.75,55.25 118.75,87 E31.1 | 117.47,53.98 117.47,52.07 119.38,50.17 119.38,48.9 121.28,46.99 121.28,43.18 IC2.6
N$39
  Top 0.254: C5.1 R30.1
  Bottom 0.254: R30.1 E37.3
N$40
  Top 0.254: E37.6 97.16,113.67 97.16,120.02 E37.2 | E40.5 80.64,114.94 80.64,116.21 E40.4 79.38,118.75 79.38,120.02 E40.2 80.64,122.56 80.64,123.83 E40.1
  Bottom 0.254: E37.2 97.79,121.92 96.52,123.19 83.82,123.19 82.55,124.46 E40.1
N$41
  Top 0.254: E52.3 20.32,53.34 20.32,78.74 E53.11
  Bottom 0.254: E52.11 19.05,45.72 16.51,48.26 E52.3 | E53.3 19.05,83.82 21.59,81.28 E53.11 24.13,81.28 27.94,77.47 33.02,77.47 36.83,73.66 E49.8
N$42
  Top 0.254: E3.9 PAD1.1
N$43
  Top 0.254: E3.10 PAD2.1
N$44
  Top 0.254: E3.12 PAD3.1
N$45
  Top 0.254: E3.13 PAD4.1
N$46
  Bottom 0.254: E24.12 173.99,149.86 175.26,148.59 200.03,148.59 203.84,144.78 E15.10
N$47
  Top 0.254: E3.8 PAD5.1
N$48  (via drill 0.61)
  Top 0.254: v121.28,48.26 122.56,48.26 122.56,45.72 IC2.7
  Bottom 0.254: v121.28,48.26 117.47,52.07 105.41,52.07 104.14,50.8 100.97,50.8 100.97,49.53 102.23,48.26 E35.12
N$49
  Bottom 0.254: E35.6 100.33,40.64 100.33,41.28 103.5,41.28 104.14,41.91 113.03,41.91 114.3,43.18 IC2.3
N$50
  Top 0.254: E35.8 124.46,38.1 IC2.5
N$51  (via drill 0.61)
  Top 0.254: v75.56,45.72 75.56,50.8 69.85,50.8 67.94,48.9 67.94,45.72 IC1.2
  Bottom 0.254: v75.56,45.72 E38.4
N$52
  Bottom 0.254: IC1.6 71.75,42.55 78.11,42.55 78.74,41.91 85.09,41.91 86.36,43.18 E38.10
N$53  (via drill 0.61)
  Top 0.254: v71.75,33.02 71.75,40.01 IC1.5 | v88.27,32.39 88.9,33.02 E38.8
  Bottom 0.254: v71.75,33.02 72.39,32.39 v88.27,32.39
N$54
  Top 0.254: E23.11 PAD12.1
N$55
  Top 0.254: E23.10 PAD13.1
N$56
  Top 0.254: E23.13 PAD14.1
N$57
  Top 0.254: E23.12 PAD15.1
N$58
  Top 0.254: E22.9 PAD16.1
N$59
  Top 0.254: PAD17.1 E22.10
N$60
  Top 0.254: E22.12 PAD18.1
N$61
  Top 0.254: E22.13 PAD19.1
N$62
  Top 0.254: E22.8 PAD20.1
N$67  (via drill 0.61)
  Top 0.254: v138.43,91.44 137.79,92.08 137.79,143.51 138.43,144.15 138.43,152.4 139.7,153.67 E28.6
  Bottom 0.254: v138.43,91.44 13.34,91.44 13.34,78.11 E53.6
N$68  (via drill 0.61)
  Top 0.254: v135.89,69.85 136.53,70.49 136.53,143.51 134.62,145.42 E28.1
  Bottom 0.254: v135.89,69.85 69.85,69.85 68.58,71.12 13.34,71.12 13.34,74.3 13.97,74.93 20.32,74.93 21.59,73.66 E53.8
N$71
  Top 0.254: E24.9 PAD27.1
N$72
  Top 0.254: E24.10 PAD28.1
N$73  (via drill 0.61)
  Top 0.254: v222.88,176.53 225.43,173.99 225.43,148.59 231.14,142.88 JP4.1
  Bottom 0.254: v222.88,176.53 211.46,176.53 211.46,174.63 E12.6
N$74
  Top 0.254: E24.11 PAD29.1
N$75
  Top 0.254: E24.8 PAD30.1
N$76
  Top 0.254: E37.9 PAD31.1
N$77
  Top 0.254: E37.10 PAD32.1
N$78
  Top 0.254: E37.8 PAD33.1
N$79
  Top 0.254: E37.12 PAD34.1
N$80
  Top 0.254: E37.13 PAD35.1
N$81
  Top 0.254: E37.11 PAD36.1
N$82
  Top 0.254: E40.9 PAD37.1
N$83
  Top 0.254: E40.10 PAD38.1
N$84
  Top 0.254: E40.12 PAD39.1
N$85
  Top 0.254: E40.13 PAD40.1
N$86
  Top 0.254: E40.8 PAD41.1
N$87
  Top 0.254: E49.12 PAD42.1
N$88
  Top 0.254: E49.13 PAD43.1
N$89
  Top 0.254: E49.11 PAD44.1
N$92
  Bottom 0.254: E24.6 166.37,142.24 167.64,140.97 182.88,140.97 186.69,144.78 E20.10
N$94  (via drill 0.61)
  Top 0.254: v203.84,186.69 237.49,186.69 237.49,127.64 236.22,126.37 236.22,111.76 E7.8
  Bottom 0.254: v203.84,186.69 196.85,186.69 191.13,180.98 134.62,180.98 E30.1
N$96  (via drill 0.61)
  Top 0.254: v203.2,111.76 203.2,88.9 E13.13
  Bottom 0.254: v203.2,111.76 E14.6
N$100  (via drill 0.61)
  Top 0.254: v203.2,74.93 201.93,76.2 201.93,139.07 v202.56,139.7
  Bottom 0.254: v203.2,74.93 241.3,74.93 245.11,78.74 E2.5 | v202.56,139.7 200.03,142.24 E15.6
N$101  (via drill 0.61)
  Top 0.254: v206.38,130.18 206.38,139.07 E15.8
  Bottom 0.254: v206.38,130.18 257.81,130.18 257.81,90.17 E2.13
N$103  (via drill 0.61)
  Top 0.254: v226.69,151.13 232.41,145.42 232.41,144.15 233.68,142.88 JP4.3
  Bottom 0.254: v226.69,151.13 219.71,151.13 219.07,151.77 215.26,151.77 214.63,152.4 E11.2
N$104  (via drill 0.61)
  Top 0.254: v151.13,46.99 149.86,48.26 v149.86,141.61
  Bottom 0.254: v151.13,46.99 193.68,46.99 194.31,46.36 208.91,46.36 212.09,43.18 E8.5 | v149.86,141.61 151.76,143.51 177.8,143.51 179.07,142.24 E20.6
N$108  (via drill 0.61)
  Top 0.254: v224.16,148.59 v224.16,170.18
  Bottom 0.254: v224.16,148.59 215.9,148.59 214.63,149.86 E11.3 | v224.16,170.18 E12.8
N$109  (via drill 0.61)
  Top 0.254: v202.56,57.15 201.29,58.42 v201.29,139.7
  Bottom 0.254: v202.56,57.15 213.36,57.15 219.71,50.8 E8.13 | v201.29,139.7 200.03,140.97 190.5,140.97 189.23,139.7 E20.8
N$111
  Bottom 0.254: E11.4 219.71,140.97 234.31,140.97 235.59,142.24 JP4.5
N$113  (via drill 0.61)
  Top 0.254: v203.84,157.48 203.84,180.98 E16.13
  Bottom 0.254: v203.84,157.48 JP3.2 JP3.4
N$128
  Top 0.254: JP2.4 JP2.6
  Bottom 0.254: E16.2 204.47,176.53 207.01,176.53 212.09,171.45 217.17,171.45 219.71,168.91 229.24,168.91 230.5,170.18 JP2.2 JP2.4
N$129
  Top 0.254: JP1.2 JP1.4
  Bottom 0.254: E16.1 199.39,185.42 200.66,184.15 229.24,184.15 230.5,182.88 JP1.2
N$132
  Bottom 0.254: E16.12 207.01,180.34 208.28,181.61 218.44,181.61 219.71,180.34 E12.12
VCC  (via drill 0.61)
  Top 0.635: E50.8 22.86,163.83 21.59,165.1 21.59,180.34 22.86,181.61 E51.8 29.84,189.87 50.8,189.87 E46.8 50.8,184.15 49.53,182.88 49.53,172.72 50.8,171.45 E45.8 | 80.01,167.64 80.01,157.48 78.74,156.21 E41.8 | 80.01,167.64 78.74,168.91 E42.8 | 80.01,167.64 80.01,182.88 78.74,184.15 E43.8 | E28.8 134.62,156.21 135.89,157.48 135.89,167.64 134.62,168.91 E29.8 134.62,171.45 133.35,172.72 133.35,182.88 134.62,184.15 E30.8 | E40.14 90.17,124.46 93.98,128.27 R30.2 | 107.95,157.48 106.68,156.21 E32.8 | 107.95,157.48 107.95,167.64 | 107.95,167.64 106.68,168.91 E33.8 | 107.95,167.64 107.95,182.88 106.68,184.15 E34.8 | 107.95,157.48 107.95,125.73 E37.14 111.76,124.46 R28.2 111.76,92.71 107.95,88.9 E36.14 | E8.14 222.25,53.34 226.06,57.15 R13.1 | 189.87,53.98 193.04,57.15 R5.1 | 189.87,53.98 189.23,53.34 E17.14 | R8.1 160.02,57.79 156.21,53.98 156.21,53.34 E26.14 | v190.5,19.05 189.87,19.69 189.87,53.98 | E16.14 207.65,183.52 207.65,156.85 E15.14 207.65,153.04 207.65,126.37 E14.14 207.65,122.56 207.65,90.81 E13.14 | R1.1 259.08,160.02 E4.14 255.91,153.04 255.91,126.37 E3.14 | E9.14 222.25,88.9 226.06,92.71 R15.1 | R9.1 43.18,57.79 39.37,53.98 39.37,53.34 E48.14 | R11.1 193.04,93.35 189.23,89.54 189.23,88.9 E18.14 | E31.14 125.73,88.9 129.54,92.71 R26.2 | E44.14 72.39,88.9 76.2,92.71 R22.2 | E39.14 90.17,88.9 93.98,92.71 R20.2 | E52.14 24.77,55.25 24.77,87 E53.14 | v87,20.32 87,51.44 E38.14 | R3.1 259.08,59.06 255.91,62.23 255.91,87 E2.14
  Bottom 0.635: E46.8 55.24,189.87 74.3,189.87 E43.8 83.19,189.87 111.12,189.87 | R17.1 149.22,185.42 147.32,187.33 136.53,187.33 E30.8 130.18,189.87 111.12,189.87 | E37.14 105.41,124.46 104.14,125.73 91.44,125.73 90.17,124.46 E40.14 | E34.8 111.12,189.87 | 241.3,54.61 245.11,58.42 253.37,58.42 | 241.3,54.61 240.03,53.34 E5.14 | R3.1 253.37,58.42 | 253.37,58.42 253.37,53.98 E1.14 | 241.3,54.61 223.52,54.61 222.25,53.34 E8.14 | 152.4,54.61 142.24,54.61 140.97,53.34 E27.14 | 152.4,54.61 153.67,53.34 E26.14 | 170.18,54.61 171.45,53.34 E21.14 | 170.18,54.61 152.4,54.61 | 170.18,54.61 185.42,54.61 186.69,53.34 E17.14 | v190.5,19.05 190.5,13.97 U$1.BA2 | R13.1 R5.1 | E16.14 207.01,185.42 208.28,186.69 218.44,186.69 219.71,185.42 E12.14 | 185.42,156.21 175.26,156.21 173.99,154.94 E24.14 | 185.42,156.21 186.69,154.94 E20.14 | 203.2,156.21 204.47,154.94 E15.14 | 203.2,156.21 185.42,156.21 | 203.2,156.21 218.44,156.21 219.71,154.94 E11.14 | E23.14 177.8,124.46 179.07,125.73 185.42,125.73 186.69,124.46 E19.14 195.58,124.46 196.85,125.73 208.28,125.73 | 208.28,125.73 207.01,124.46 E14.14 | 208.28,125.73 218.44,125.73 | 218.44,125.73 219.71,124.46 E10.14 | 236.22,125.73 237.49,124.46 E7.14 | 218.44,125.73 236.22,125.73 | 236.22,125.73 251.46,125.73 252.73,124.46 E3.14 | R15.1 232.41,93.98 237.49,88.9 E6.14 240.03,88.9 241.3,87.63 250.19,87.63 | 250.19,87.63 251.46,87.63 252.73,88.9 E2.14 | 250.19,87.63 252.73,85.09 264.16,85.09 264.16,24.77 261.62,22.23 261.62,13.97 U$1.AA2 | U$1.DA2 58.42,13.97 58.42,20.32 v87,20.32 121.92,20.32 128.27,13.97 U$1.CA2 | 35.56,52.07 25.4,52.07 24.13,53.34 E52.14 | 35.56,52.07 36.83,53.34 E48.14
  Bottom 0.635: 53.34,52.07 54.61,53.34 E47.14 | 35.56,52.07 53.34,52.07 | 53.34,52.07 70.48,52.07 | 70.48,52.07 86.36,52.07 87.63,53.34 E38.14 90.17,53.34 91.44,52.07 104.14,52.07 105.41,53.34 E35.14 118.11,53.34 123.19,48.26 IC2.8 | 185.42,87.63 179.07,87.63 177.8,88.9 E22.14 | 185.42,87.63 186.69,88.9 E18.14 | 185.42,87.63 203.2,87.63 204.47,88.9 E13.14 | E53.14 24.13,88.9 25.4,90.17 35.56,90.17 36.83,88.9 E49.14 39.37,88.9 40.64,90.17 68.58,90.17 69.85,88.9 E44.14 | R22.2 R20.2 R28.2 R26.2 R23.1 R11.1 214.63,93.98 219.71,88.9 E9.14 | 70.48,52.07 70.48,48.9 IC1.8

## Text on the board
Bottom: VRS
tPlace: Fold in ECOs. | WARNING: DO NOT USE WITH OMNIBUS CPU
